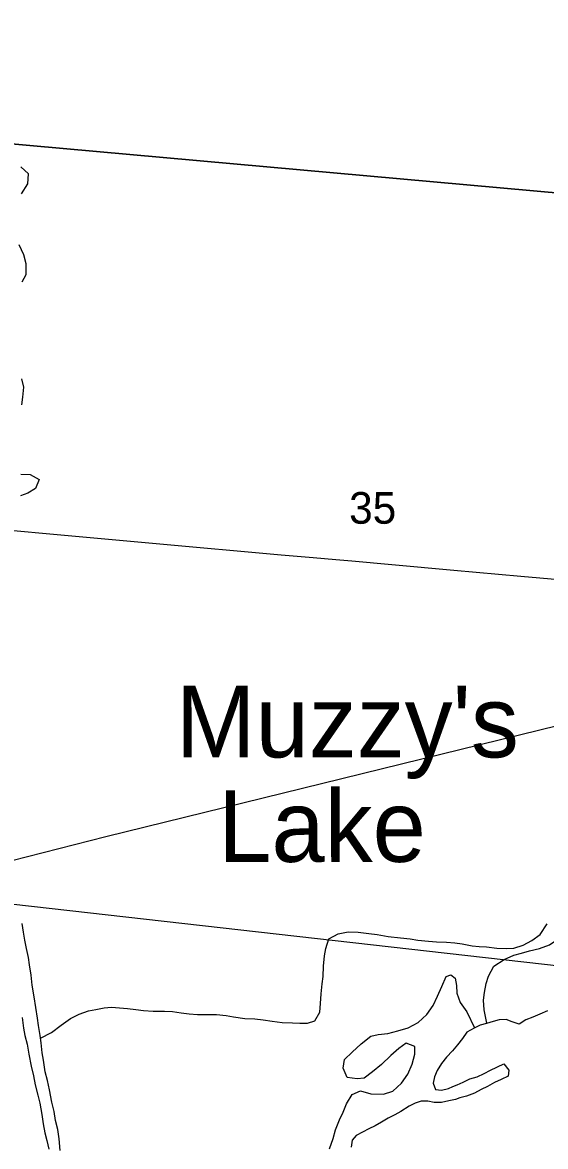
# Model space of a CAD drawing. Extents: x 0 to 1067, y 0 to 440.
# Drawn here: x 227.4 to 268.9, y 51.6 to 140.8 of the extents above; entities that cross this region are included whole.
import ezdxf

# ---------------------------------------------------------------- set-up
doc = ezdxf.new("R2010")
doc.units = 0
for name, color, linetype in [('GM_X_Major_River', 7, 'Continuous'), ('GM_X_Minor_Lake', 7, 'Continuous'), ('GM_X_Minor_Lake_Text', 7, 'Continuous'), ('GM_X_Minor_River', 7, 'Continuous'), ('GM_X_Rail_Line', 7, 'Continuous'), ('GM_X_Section', 7, 'Continuous'), ('GM_X_Section_Text', 7, 'Continuous'), ('GM_X_US_Route', 7, 'Continuous')]:
    doc.layers.add(name, color=color, linetype=linetype)

msp = doc.modelspace()

# ---------------------------------------------------------------- linework, layer by layer
at = {"layer": 'GM_X_Major_River'}
for points in [[(230.403, 51.282), (230.328, 52.197), (230.205, 52.952), (230.035, 53.662), (229.911, 54.372), (229.741, 55.105), (229.554, 56.09), (229.384, 56.823), (229.214, 57.534), (229.071, 58.449), (228.967, 59.021), (228.89, 59.821), (228.81, 60.416), (228.687, 61.194), (228.606, 61.766), (228.462, 62.636), (228.34, 63.46), (228.174, 64.398), (228.097, 65.198), (227.975, 66.022), (227.894, 66.594), (227.724, 67.305), (227.599, 67.969), (227.497, 68.61), (227.372, 69.296)], [(227.396, 61.833), (227.495, 60.987), (227.598, 60.392), (227.769, 59.727), (227.914, 58.926), (228.102, 57.964), (228.271, 57.208), (228.418, 56.498), (228.632, 55.672), (228.78, 55.031), (228.947, 54.138), (229.048, 53.406), (229.171, 52.673), (229.343, 52.077), (229.491, 51.389)]]:
    msp.add_lwpolyline(points, dxfattribs=at)
at = {"layer": 'GM_X_Minor_Lake'}
for points in [[(269.041, 62.349), (268.423, 62.107), (267.873, 61.863), (267.323, 61.642), (266.795, 61.308), (266.228, 61.475), (265.752, 61.686), (265.205, 61.648), (264.725, 61.517), (264.199, 61.365), (263.696, 61.212), (263.214, 60.99), (262.64, 60.656), (262.292, 60.159), (261.898, 59.663), (261.504, 59.19), (261.019, 58.672), (260.624, 58.176), (260.298, 57.634), (260.086, 57.135), (259.965, 56.635), (260.163, 56.132), (260.641, 56.08), (261.189, 56.209), (261.533, 56.364), (261.877, 56.496), (262.358, 56.695), (262.885, 56.962), (263.457, 57.136), (264.007, 57.38), (264.512, 57.647), (265.567, 58.157), (265.97, 57.65), (265.918, 57.172)], [(265.918, 57.172), (265.367, 56.906), (264.84, 56.662), (264.289, 56.351), (263.762, 56.107), (263.257, 55.84), (262.616, 55.598), (262.09, 55.446), (261.747, 55.336), (261.221, 55.229), (260.627, 55.1), (260.058, 55.085), (259.558, 55.205), (259.012, 55.19), (258.554, 55.036), (258.072, 54.792), (257.406, 54.368), (256.924, 54.101), (256.397, 53.857), (255.868, 53.522), (255.363, 53.233), (254.881, 52.989), (254.377, 52.745), (253.872, 52.478), (253.548, 52.095)], [(253.548, 52.095), (253.472, 51.549)]]:
    msp.add_lwpolyline(points, dxfattribs=at)
at = {"layer": 'GM_X_Minor_River'}
for points in [[(227.32, 127.159), (227.835, 127.971), (227.894, 128.767), (227.267, 129.325)], [(227.379, 120.186), (227.708, 120.773), (227.7, 121.616), (227.508, 122.326), (227.158, 123.129)], [(227.335, 112.486), (227.483, 111.845), (227.423, 111.049), (227.321, 110.436)], [(227.27, 104.923), (228.021, 104.91), (228.743, 104.51), (228.434, 103.786), (227.836, 103.432), (227.24, 103.214)], [(264.227, 61.373), (264.009, 62.438), (263.951, 63.213), (264.028, 63.805), (264.174, 64.532), (264.365, 65.122), (264.785, 65.891), (265.59, 66.427), (266.369, 66.782), (266.964, 66.933), (267.604, 67.107), (268.404, 67.302), (269.205, 67.587), (269.941, 68.102), (270.724, 68.729), (271.505, 69.243), (272.218, 69.758), (272.275, 70.577), (272.541, 71.062), (273.059, 72.868), (272.93, 73.462), (273.04, 74.828)], [(228.841, 60.187), (229.701, 60.633), (230.463, 61.212), (231.224, 61.746), (231.913, 62.098), (232.647, 62.359), (233.218, 62.463), (233.88, 62.589), (234.474, 62.647), (235.11, 62.59), (235.747, 62.557), (236.384, 62.477), (236.997, 62.376), (237.77, 62.34), (238.659, 62.347), (239.296, 62.314), (239.977, 62.211), (240.614, 62.132), (241.296, 62.074), (242.207, 62.082), (242.799, 62.071), (243.549, 61.99), (244.139, 61.889), (245.025, 61.76), (245.822, 61.724), (246.481, 61.644), (247.208, 61.54), (248.003, 61.436), (248.822, 61.399), (249.391, 61.389), (250.006, 61.379), (250.579, 61.574), (250.978, 62.251), (251.035, 62.933), (251.094, 63.707), (251.177, 64.503), (251.255, 65.094), (251.27, 65.915), (251.352, 66.711), (251.454, 67.301), (251.695, 68.072), (252.431, 68.469), (253.231, 68.615), (254.027, 68.602), (254.868, 68.496), (255.527, 68.417), (256.413, 68.265), (257.367, 68.158), (258.14, 68.076), (258.753, 67.975), (259.595, 67.892), (260.231, 67.835), (261.028, 67.799), (261.687, 67.742), (262.256, 67.687), (263.05, 67.514), (263.618, 67.459), (264.209, 67.426), (265.005, 67.344), (265.779, 67.308), (266.371, 67.321), (267.104, 67.559), (267.794, 67.935), (268.463, 68.425), (269.002, 69.259)], [(251.739, 51.412), (252.046, 52.229), (252.216, 52.933), (252.545, 53.726), (252.827, 54.314), (253.109, 54.971), (253.552, 55.718), (254.217, 56.005), (255.034, 55.766), (256.036, 55.753), (256.768, 55.994), (257.46, 56.623), (257.971, 57.345), (258.301, 58.138), (258.516, 58.91), (258.525, 59.525), (257.822, 59.785), (257.247, 59.383), (256.625, 58.821), (255.863, 58.102), (255.149, 57.519), (254.504, 57.026), (253.934, 56.966), (253.138, 57.067), (252.83, 57.8), (252.93, 58.505), (253.553, 59.09), (254.269, 59.741), (255.029, 60.346), (255.6, 60.475), (256.375, 60.556), (257.176, 60.773), (257.976, 61.014), (258.779, 61.436), (259.471, 62.065), (259.959, 62.787), (260.311, 63.512), (260.663, 64.282), (260.993, 65.075), (261.363, 65.225), (261.72, 64.952), (261.826, 64.358), (261.84, 63.765), (262.103, 63.01), (262.64, 62.274), (263.247, 61.005)]]:
    msp.add_lwpolyline(points, dxfattribs=at)
at = {"layer": 'GM_X_Rail_Line'}
msp.add_lwpolyline([(131, 79.259), (180.664, 74.419), (191.442, 73.556), (204.287, 72.463), (208.637, 72.02), (213.57, 72.111), (218.742, 72.551), (225.299, 73.956), (234.013, 76.199), (273.05, 85.78), (280.267, 87.514)], dxfattribs=at)
at = {"layer": 'GM_X_Section'}
for points in [[(230.143, 191.616), (293.305, 184.745), (289.359, 125.481), (225.317, 131.247)], [(225.317, 131.247), (289.359, 125.481), (286.308, 90.531), (282.115, 64.529), (220.613, 71.485)]]:
    msp.add_lwpolyline(points, close=True, dxfattribs=at)
at = {"layer": 'GM_X_US_Route'}
for points in [[(222.364, 100.836), (222.926, 100.786), (226.418, 100.484), (229.871, 100.167), (238.003, 99.432), (247.918, 98.545), (250.444, 98.323), (252.263, 98.164), (253.517, 98.052)], [(253.517, 98.052), (256.682, 97.767), (261.619, 97.312), (266.931, 96.844), (269.932, 96.575)]]:
    msp.add_lwpolyline(points, dxfattribs=at)

# ---------------------------------------------------------------- texts
at = {"layer": 'GM_X_Minor_Lake_Text'}
for s, rotation, p in [("Muzzy's", 0.00833, (239.559, 82.464)), ('Lake', 0.00808, (242.919, 74.175))]:
    msp.add_text(s, height=5.6818, rotation=rotation, dxfattribs=at).set_placement(p)
at = {"layer": 'GM_X_Section_Text'}
msp.add_text('35', height=2.5114, rotation=0.00001, dxfattribs=at).set_placement((253.304, 101.001))

doc.saveas('drawing.dxf')
